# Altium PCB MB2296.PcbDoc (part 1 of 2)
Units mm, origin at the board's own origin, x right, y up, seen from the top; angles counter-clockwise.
Board outline 43 x 47.02 mm, 4 copper layers (Top Layer, Internal 1, Internal 2, Bottom Layer), stack 1.565 mm thick; 91 components, 90 nets, 355 pads, 438 vias.
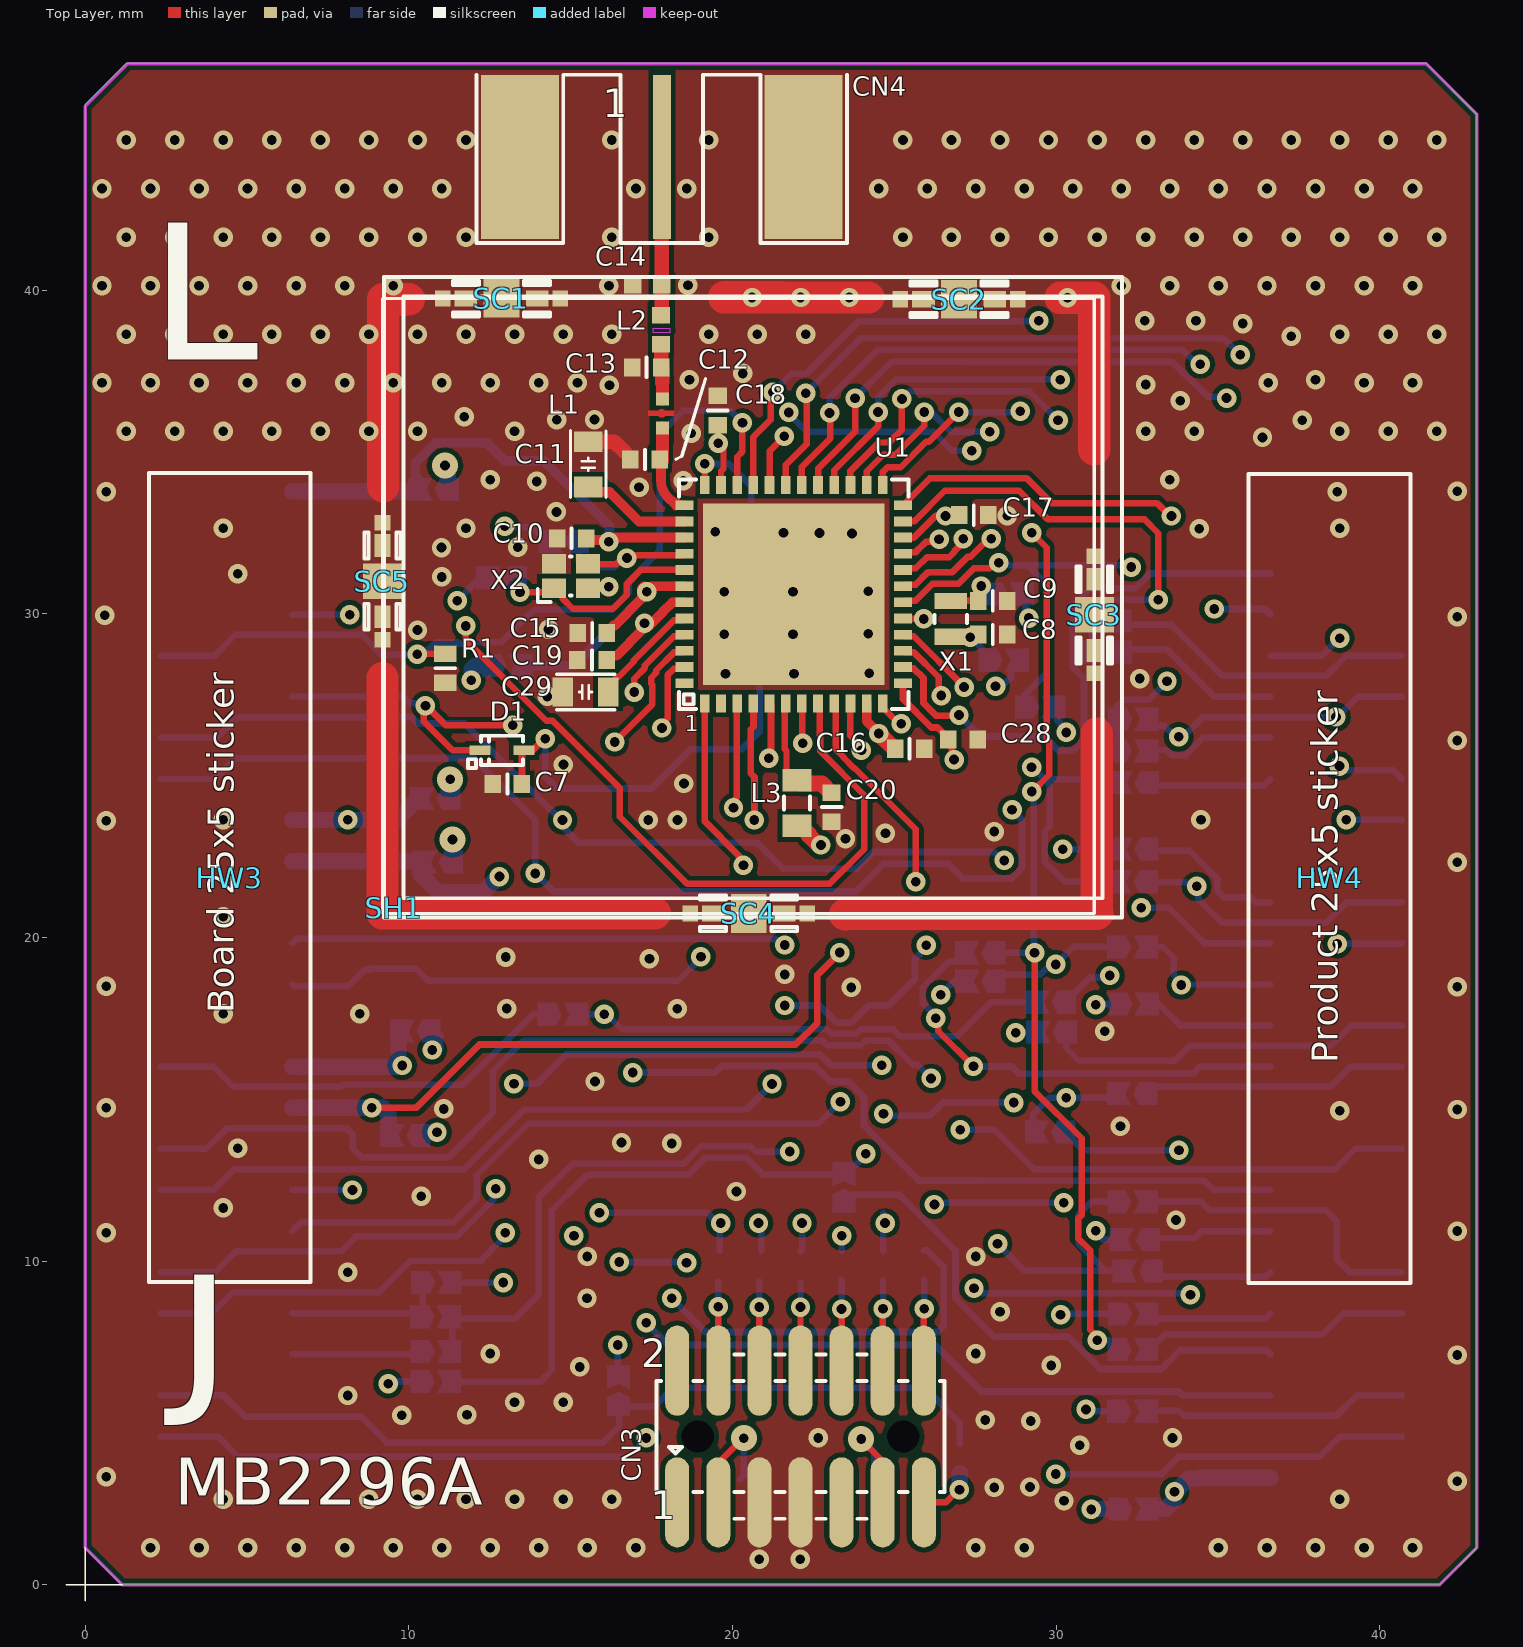
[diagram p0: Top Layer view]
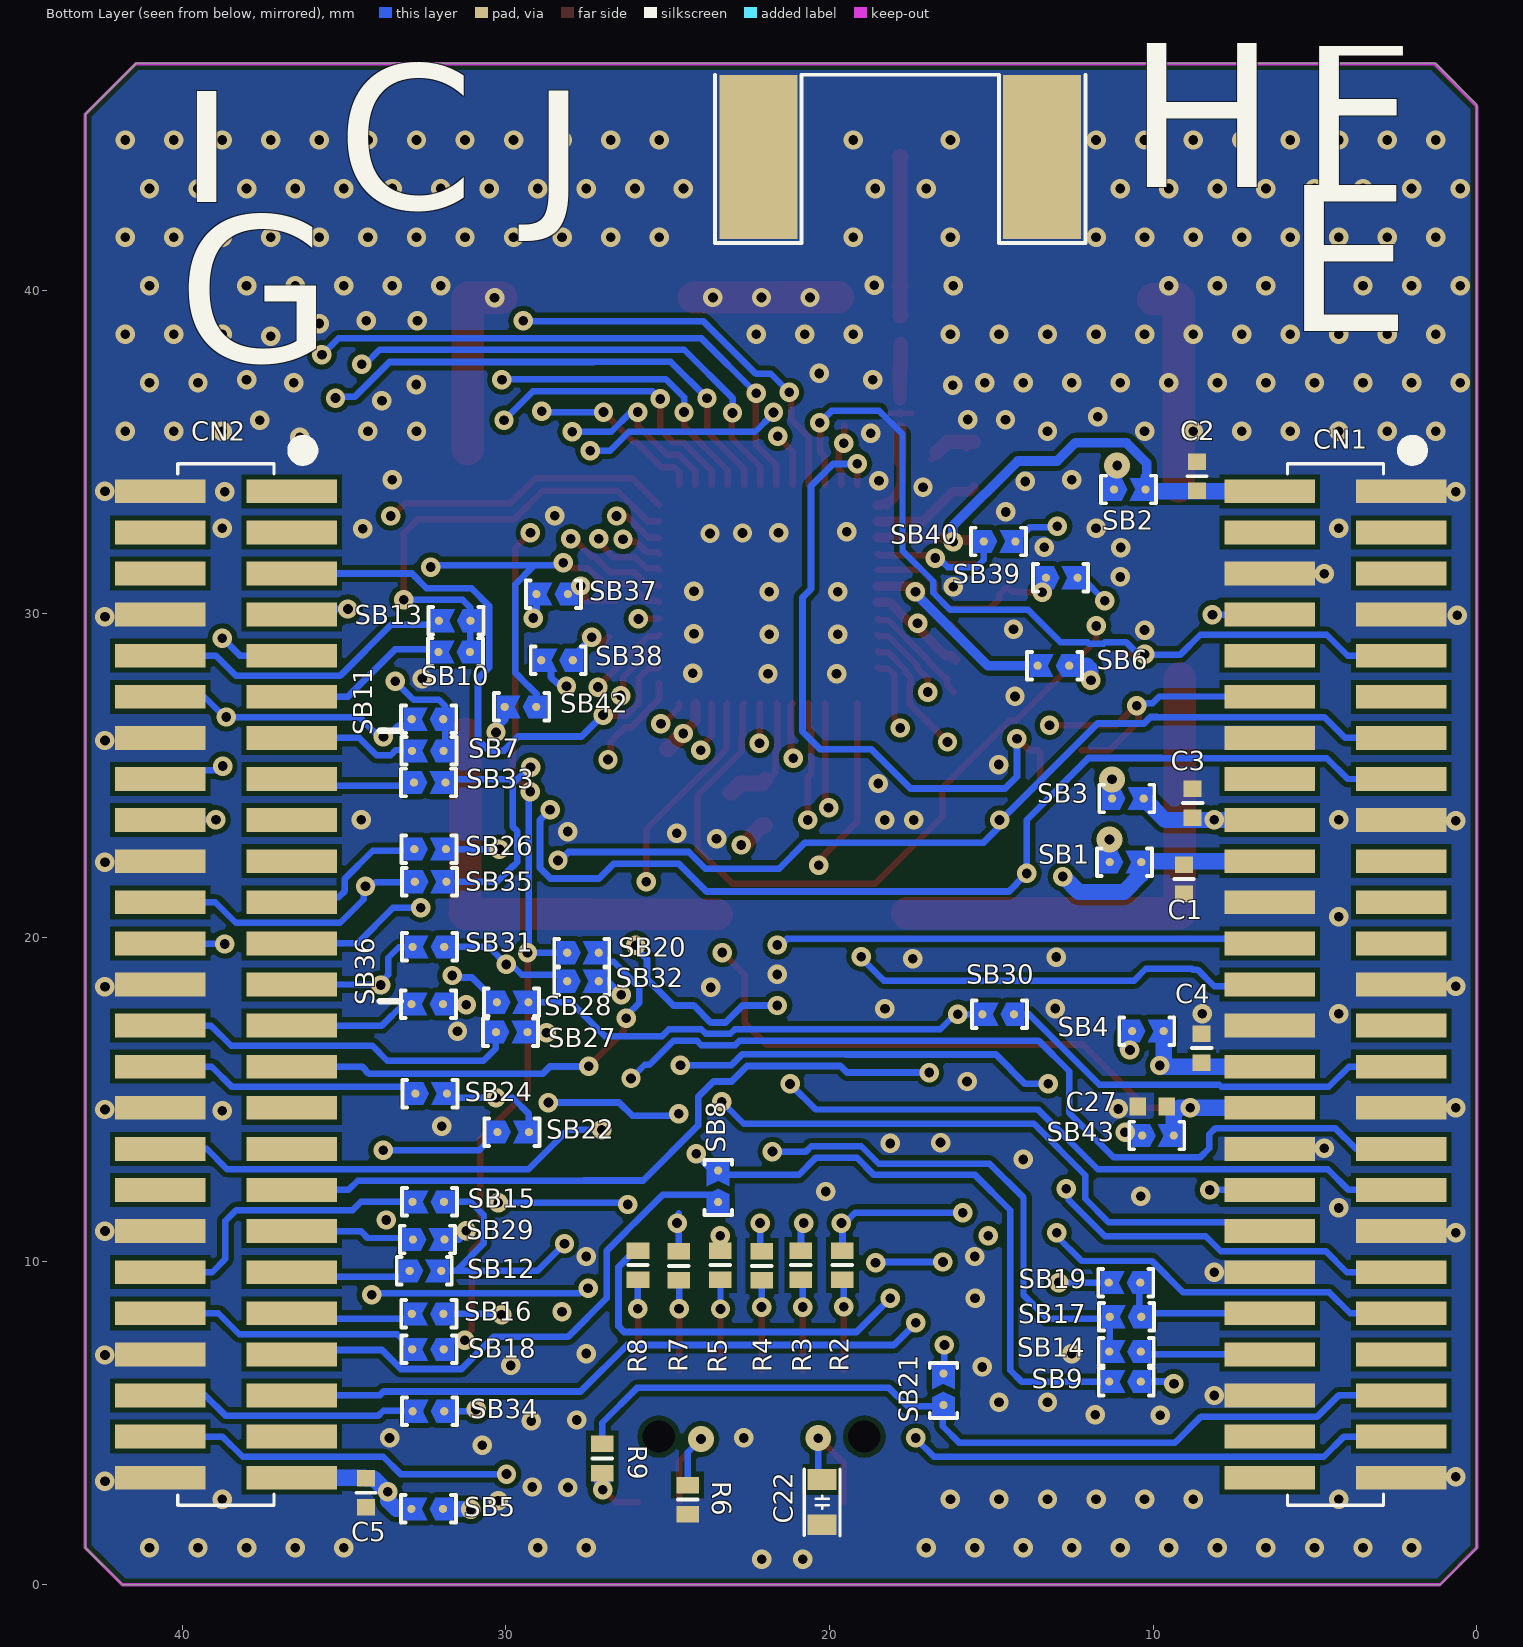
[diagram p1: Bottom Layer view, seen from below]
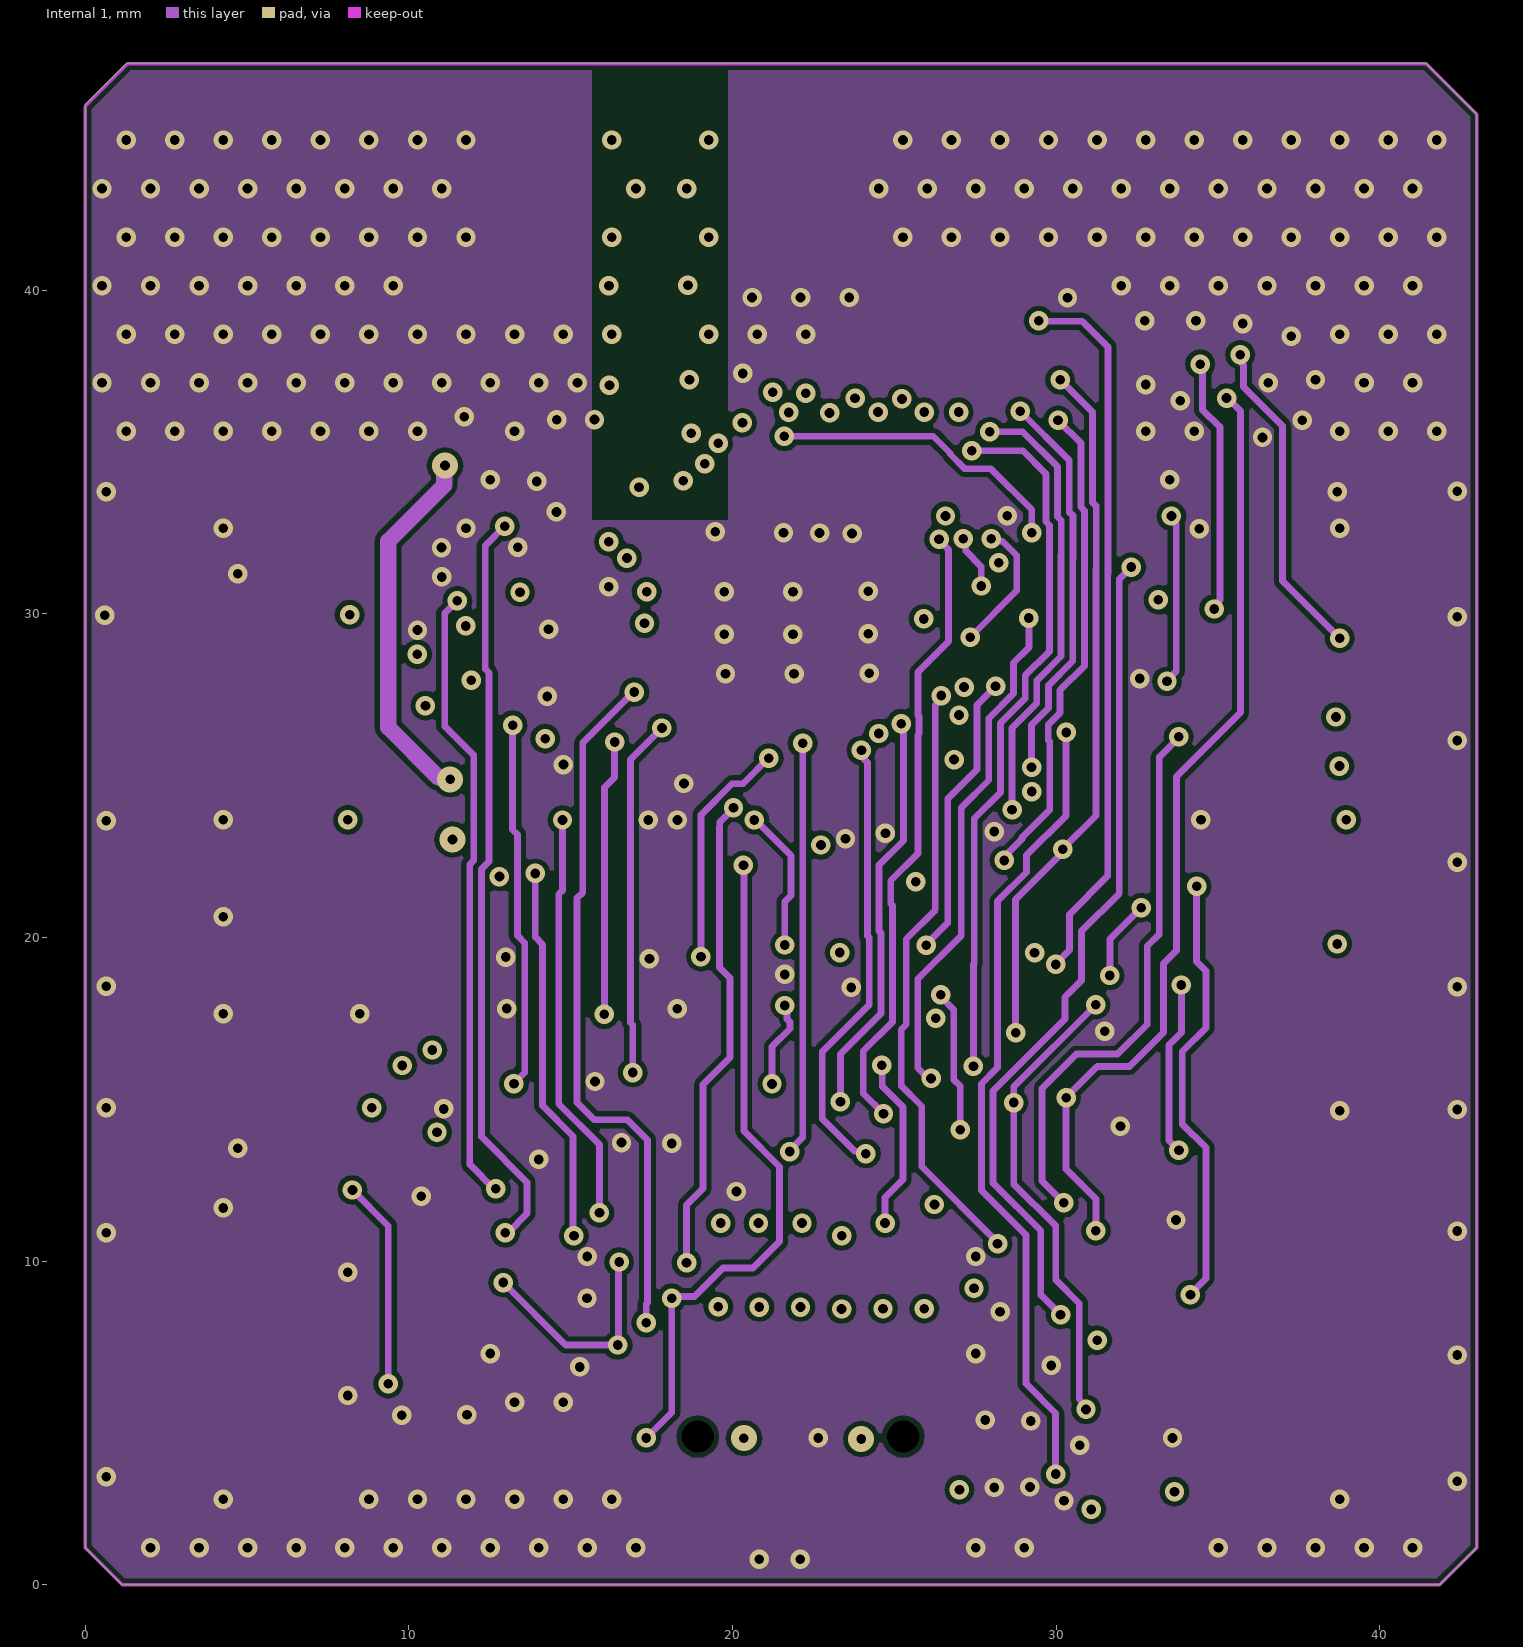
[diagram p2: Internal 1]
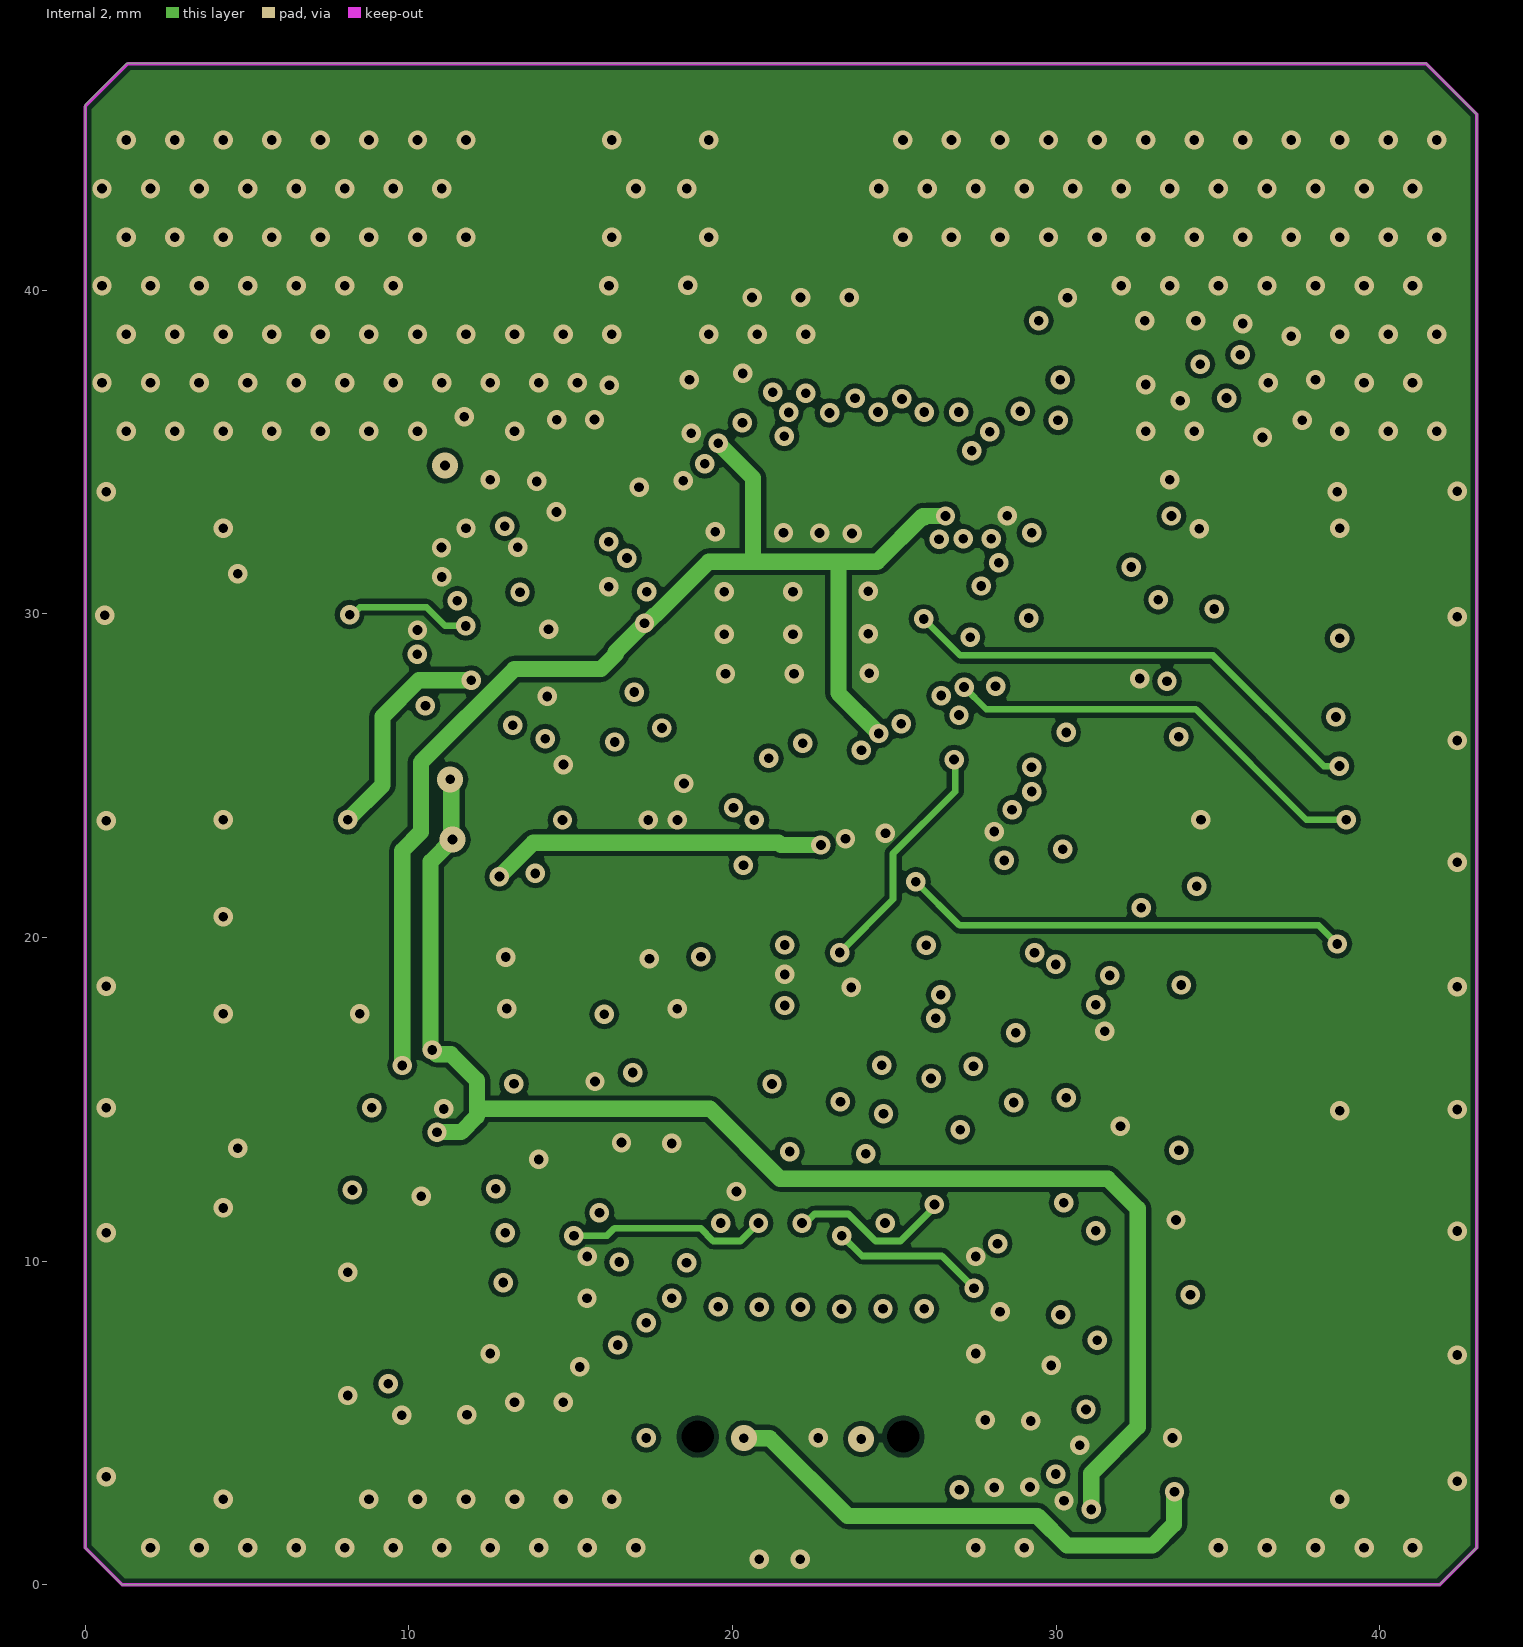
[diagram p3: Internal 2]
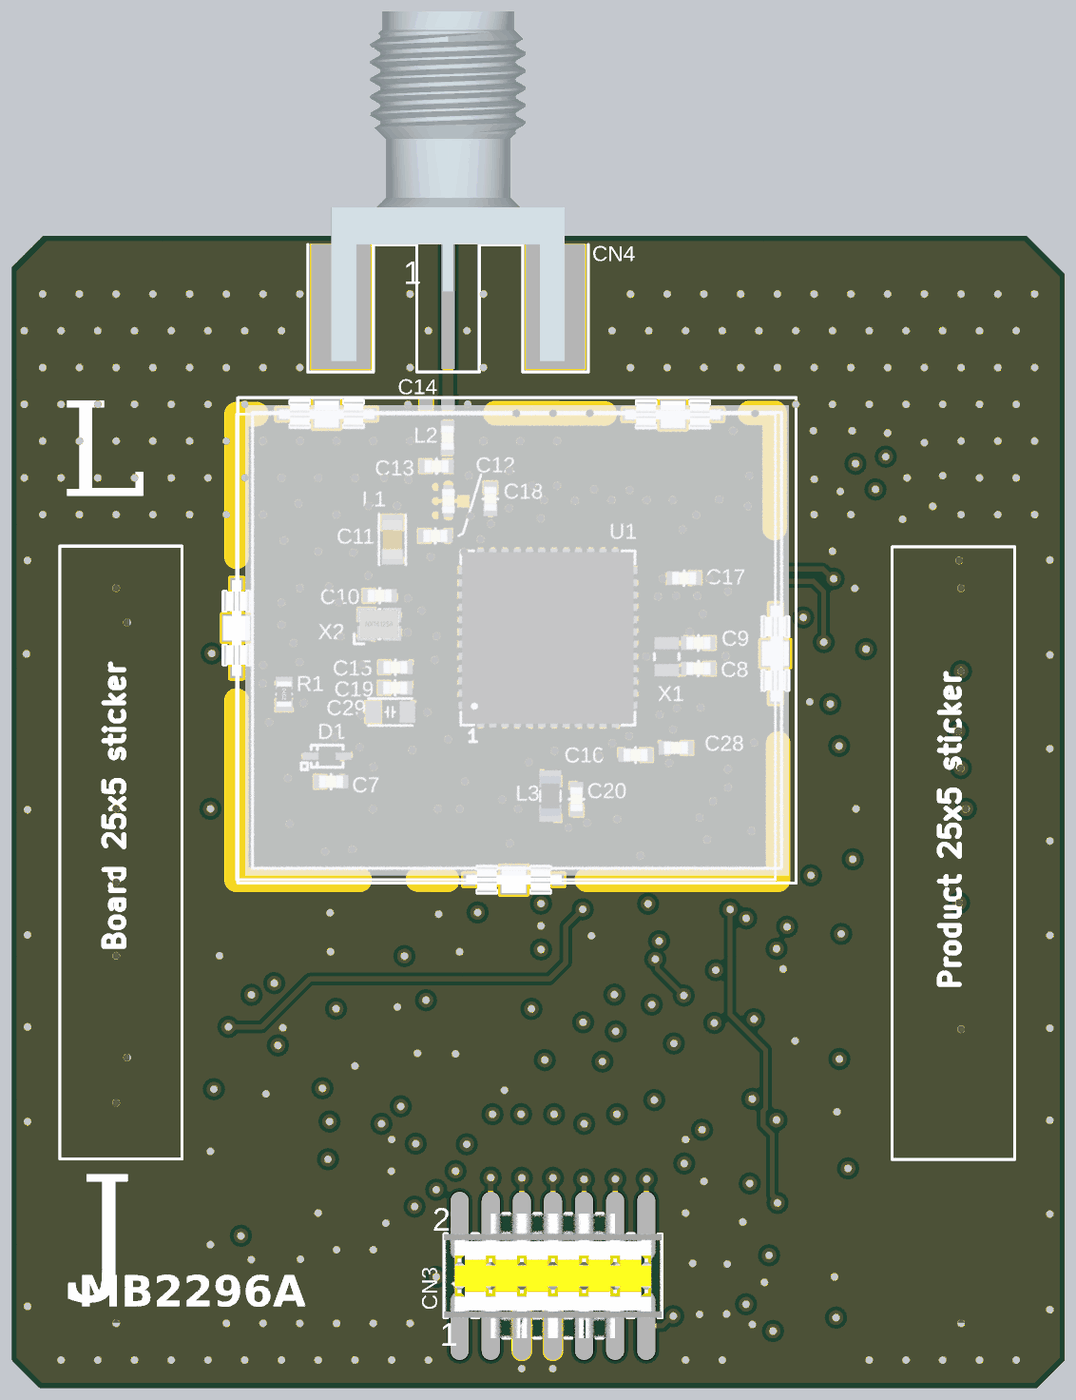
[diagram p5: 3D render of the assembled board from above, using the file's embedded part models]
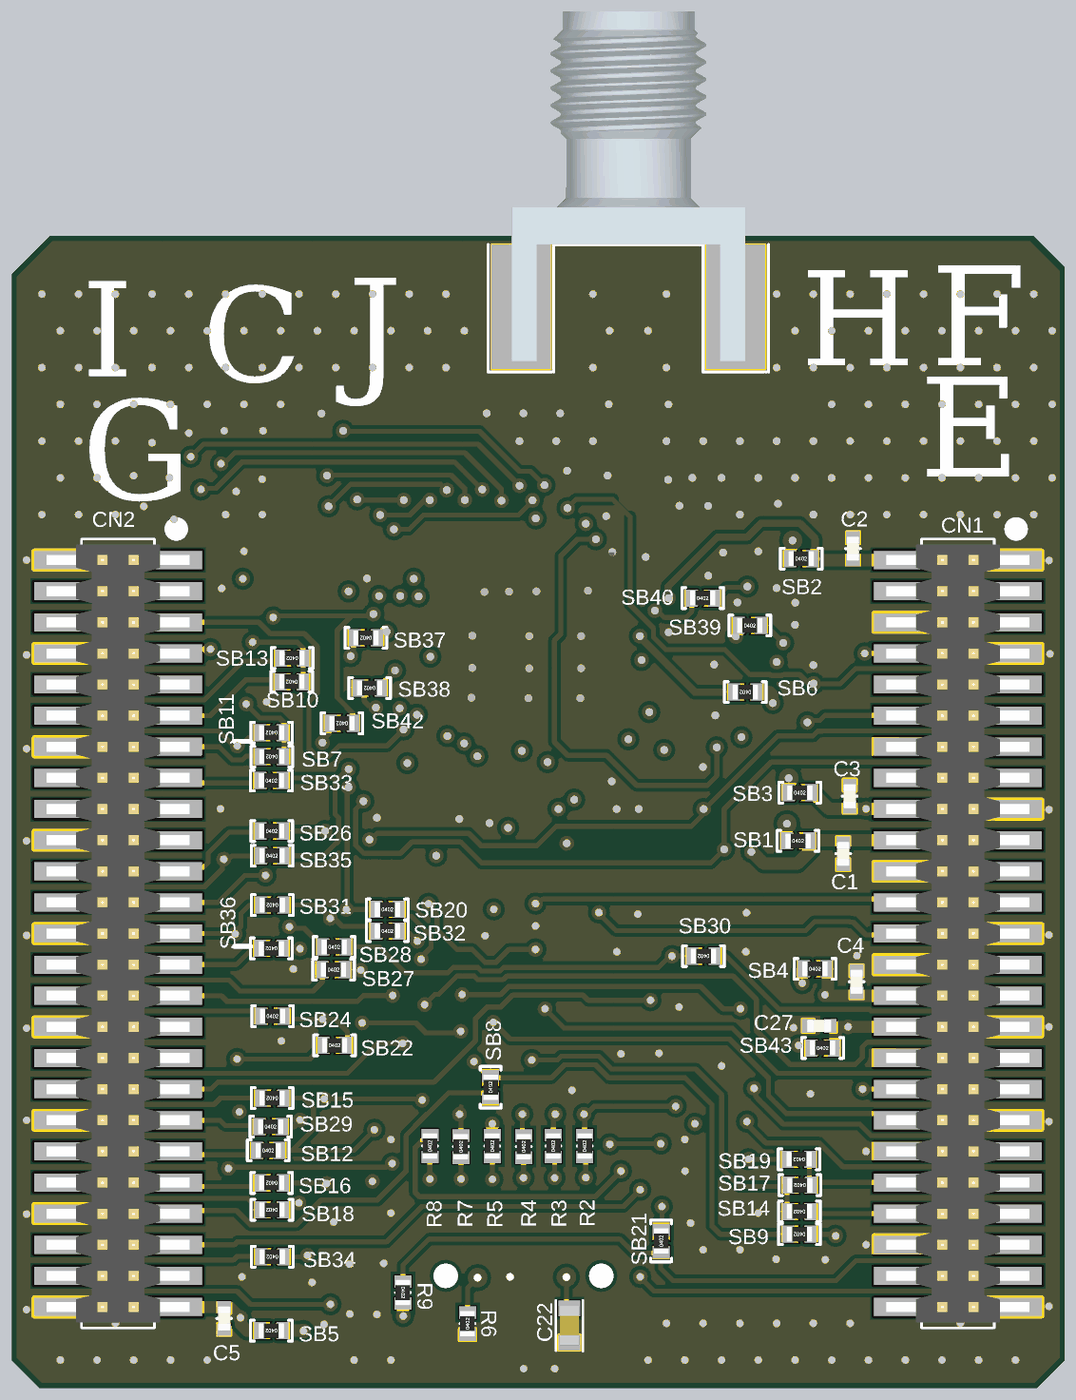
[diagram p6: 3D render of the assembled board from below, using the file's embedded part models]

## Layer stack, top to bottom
Top Solder: solder mask 0.0178, Solder Resist, Dk 4.2
Top Layer: signal copper 0.0406
Dielectric 1: core 0.0762, FR-4, Dk 3.7
Internal 1: signal copper 0.0305
Dielectric 3: prepreg 1.27, Dk 4.5
Internal 2: signal copper 0.0305
Dielectric 2: core 0.0762, FR-4, Dk 3.7
Bottom Layer: signal copper 0.0406
Bottom Solder: solder mask 0.0178, Solder Resist, Dk 4.2

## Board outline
0,1.139 1.139,0 41.852,0 43.001,1.141 43,39.982 43,45.443 41.427,47.015 1.273,47.015 0.003,45.745 0,45.72

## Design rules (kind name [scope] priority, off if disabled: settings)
Clearance "RF Path IPD" [WithinRoom('IPD')] p1: gap=0 ignorepadtopadclearanceinfootprint=FALSE
Clearance "RF Path 3" [InNet('NetC12_2')] p2: gap=0.13 ignorepadtopadclearanceinfootprint=FALSE
Clearance "RF Path 2" [InNet('NetC13_2')] p3: gap=0.13 ignorepadtopadclearanceinfootprint=FALSE
Clearance "RF Path 1" [InNet('ANT')] p4: gap=0.13 ignorepadtopadclearanceinfootprint=FALSE
Clearance [All] p5: gap=0.15 ignorepadtopadclearanceinfootprint=FALSE
ComponentClearance [All] p1: gap=0.1 collisioncheckmode=3 verticalgap=0.1 showdistances=FALSE
HoleSize [All] p1: absolutevalues=TRUE maxlimit=10 minlimit=0.025 maxpercent=80.000 minpercent=20.000
MatchedLengths "Schematic Matched Net Lengths_1" [InNet('GPIO36')] p1: tolerance=2 checknetsindiffpair=TRUE checkdiffpairvsdiffpair=FALSE checkxsignals=FALSE checkothers=FALSE
MatchedLengths "Schematic Matched Net Lengths" [InNet('GPIO35')] p2: tolerance=2 checknetsindiffpair=TRUE checkdiffpairvsdiffpair=FALSE checkxsignals=FALSE checkothers=FALSE
MaxMinImpedance "Schematic Impedance Constraint_1" [InNet('GPIO36')] p1: minimum=85.00 maximum=95.00
MaxMinImpedance "Schematic Impedance Constraint" [InNet('GPIO36')] p2: minimum=85.00 maximum=95.00
MinimumSolderMaskSliver [All] p1: minsoldermaskwidth=0.1
PlaneConnect [All] p1: planeconnectstyle=Relief reliefexpansion=0.508 reliefentries=4 reliefconductorwidth=0.21 reliefairgap=0.21
PolygonConnect Path_RF [InNet('NetC12_2')] p1: connectstyle=Direct reliefconductorwidth=0.254 reliefentries=4 polygonreliefangle="90 Angle" airgapwidth=0.254
PolygonConnect PolygonConnect_via [IsVia] p2: connectstyle=Direct reliefconductorwidth=0.254 reliefentries=4 polygonreliefangle="90 Angle" airgapwidth=0.254
PolygonConnect General [All] p3: connectstyle=Direct reliefconductorwidth=0.2 reliefentries=4 polygonreliefangle="90 Angle" airgapwidth=0.2
RoomDefinition IPD [False vs False] p1: confinementstyle=ConfineIn formatcopy=TRUE lockcomponents=FALSE outline 17.16,37.15 18.47,37.15 18.47,35.271 17.16,35.271
RoutingVias [All] p1: holewidth=0.3 width=0.6 viastyle="Through Hole" minholewidth=0.2 minwidth=0.5 maxholewidth=3.5 maxwidth=6.5
ShortCircuit [WithinRoom('IPD')] p1: allowed=TRUE
SilkToSilkClearance [All] p1 off: silktosilkclearance=0.2
SilkToSolderMaskClearance [IsPad] p1 off: minsilkscreentomaskgap=0.2 clearancetoexposedcopper=TRUE
SolderMaskExpansion [All] p1: expansion=0.102 istentingtop=FALSE
Width [All] p1: maxlimit=6 minlimit=0.15 preferedwidth=0.2 midlayer1_maxwidth=0.512 midlayer2_maxwidth=0.512 minimp=50.000000 maximp=50.000000 favimp=50.000000
23 further rules are at their usual default settings.

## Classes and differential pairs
component class "STM32 microcontroller I/Os & Clock": C1 C2 C3 C4 C5 C7 C8 C9 C27 CN1 CN2 D1 R1 SB1 SB2 SB3 SB4 SB5 SB7 SB8 SB9 SB10 SB11 SB12 SB13 SB14 SB15 SB16 SB17 SB18 SB19 SB20 SB21 SB22 SB24 SB26 SB27 SB28 SB29 SB30 SB31 SB32 SB33 SB34 SB35 SB36 SB37 SB38 SB39 SB40 SB42 SB43 U1 X1 X2
component class "RF & Power Management Schematic": C10 C11 C12 C13 C14 C15 C16 C17 C18 C19 C20 C22 C28 C29 CN3 CN4 L1 L2 L3 R2 R3 R4 R5 R6 R7 R8 R9 SB6 SC1 SC2 SC3 SC4 SC5 SH1
component class Project_Overview: HW2 HW3 HW4

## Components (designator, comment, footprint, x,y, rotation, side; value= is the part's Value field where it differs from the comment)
C1 "Capacitor" C0402#1 9.05,21.804 r90 bottom value=1uF
C2 "Capacitor" C0402#1 8.649,34.255 r270 bottom value=1uF
C3 "Capacitor" C0402#1 8.782,24.151 r270 bottom value=1uF
C4 "Capacitor" C0402#1 8.504,16.581 r270 bottom value=1uF
C5 "Capacitor" C0402#1 34.325,2.841 r90 bottom value=1uF
C7 "Capacitor" C0402#1 13.042,24.745 r0 top value=100nF
C8 "Capacitor" C0402#1 28.042,29.362 r180 top value=6pF
C9 "Capacitor" C0402#1 28.042,30.404 r180 top value=6pF
C10 "Capacitor" C0402#1 15.028,32.334 r180 top value=100nF
C11 "Capacitor" C0603 15.545,34.62 r270 top value=470nF
C12 "Capacitor" C0402#1 17.297,34.773 r0 top value=1.5pF
C13 "Capacitor" C0402#1 17.348,37.617 r0 top value=1.8pF
C14 "Capacitor" C0402_MURATA_GRM155_H0P5 17.366,40.157 r0 top value=1pF
C15 "Capacitor" C0402#1 15.668,29.414 r180 top value=100nF
C16 "Capacitor" C0402#1 25.474,25.831 r0 top value=100nF
C17 "Capacitor" C0402#1 27.457,33.052 r0 top value=100nF
C18 "Capacitor" C0402#1 19.546,36.287 r90 top value=100nF
C19 "Capacitor" C0402#1 15.658,28.575 r180 top value=100nF
C20 "Capacitor" C0402#1 23.063,24.028 r90 top value=1uF
C22 "Capacitor" C0603 20.231,2.554 r90 bottom value=1uF
C27 "Capacitor" C0402#1 10.029,14.782 r180 bottom value=1uF
C28 "Capacitor" C0402#1 27.123,26.124 r0 top value=100nF
C29 "Capacitor" C0603_H0P8 15.459,27.586 r180 top value=4.7uF
CN1 "FTSH-125-02-L-DV" FTSH-125-02-L-DV 4.366,18.548 r180 bottom locked value="Header 25x2"
CN2 "FTSH-125-02-L-DV" FTSH-125-02-L-DV 38.656,18.548 r180 bottom locked value="Header 25x2"
CN3 "Header 7x2" CON_SAMTEC_FTSH-107-01-L-DV-K-A 22.101,4.579 r0 top
CN4 "mmcx" CON_SMA-RF_CINCH_142-0701-851 17.819,46.66 r0 top value=Jack_SMA_142-0701-851
D1 "SCHOTTKY_1A_2K" DIO_SOD523_1A_2K 12.879,25.784 r180 top value=BAT54KFILM
HW3 "STICKER_BOARD" STICKER_BOARD_25X5 4.464,21.854 r90 top value="Sticker board"
HW4 "STICKER_PRODUCT" STICKER_PRODUCT_25X5 38.451,21.829 r90 top value="Sticker product"
L1 "Inductor" C0402#2 17.831,36.195 r90 top value=1.8nH
L2 "Inductor" C0402#1 17.796,38.776 r90 top value=3.3nH
L3 "Inductor" IND_0603_H0P8 21.995,24.159 r90 top value="47R @ 100MHz"
R1 "Resistor" R0402 11.125,28.32 r270 top value=100K
R2 "Resistor" R0402 19.605,9.878 r90 bottom value=47R
R3 "Resistor" R0402 20.887,9.878 r90 bottom value=47R
R4 "Resistor" R0402 22.092,9.852 r90 bottom value=47R
R5 "Resistor" R0402 23.376,9.878 r90 bottom value=47R
R6 "Resistor" R0402 24.386,2.631 r90 bottom value=47R
R7 "Resistor" R0402 24.658,9.853 r90 bottom value=47R
R8 "Resistor" R0402 25.922,9.878 r90 bottom value=47R
R9 "Resistor" R0402 27.024,3.9 r270 bottom value=47R
SB1 "SB_OFF" SOLDER-BRIDGE_R0402-0R 10.893,22.329 r180 bottom
SB2 "SB_OFF" SOLDER-BRIDGE_R0402-0R 10.764,33.846 r180 bottom
SB3 "SB_OFF" SOLDER-BRIDGE_R0402-0R 10.819,24.295 r180 bottom
SB4 "SB_OFF" SOLDER-BRIDGE_R0402-0R 10.201,17.107 r180 bottom
SB5 "SB_OFF" SOLDER-BRIDGE_R0402-0R 32.397,2.343 r0 bottom
SB6 "SB_ON" SOLDER-BRIDGE_R0402-0R 13.046,28.401 r0 bottom
SB7 "SB_ON" SOLDER-BRIDGE_R0402-0R 32.378,25.767 r0 bottom
SB8 "SB_ON" SOLDER-BRIDGE_R0402-0R 23.444,12.277 r90 bottom
SB9 "SB_OFF" SOLDER-BRIDGE_R0402-0R 10.834,6.277 r0 bottom
SB10 "SB_ON" SOLDER-BRIDGE_R0402-0R 31.563,28.823 r0 bottom
SB11 "SB_ON" SOLDER-BRIDGE_R0402-0R 32.389,26.746 r0 bottom
SB12 "SB_OFF" SOLDER-BRIDGE_R0402-0R 32.525,9.698 r180 bottom
SB13 "SB_ON" SOLDER-BRIDGE_R0402-0R 31.548,29.789 r0 bottom
SB14 "SB_OFF" SOLDER-BRIDGE_R0402-0R 10.834,7.205 r0 bottom
SB15 "SB_ON" SOLDER-BRIDGE_R0402-0R 32.364,11.832 r0 bottom
SB16 "SB_OFF" SOLDER-BRIDGE_R0402-0R 32.385,8.371 r0 bottom
SB17 "SB_ON" SOLDER-BRIDGE_R0402-0R 10.82,8.28 r0 bottom
SB18 "SB_ON" SOLDER-BRIDGE_R0402-0R 32.373,7.274 r0 bottom
SB19 "SB_OFF" SOLDER-BRIDGE_R0402-0R 10.85,9.337 r0 bottom
SB20 "SB_OFF" SOLDER-BRIDGE_R0402-0R 27.658,19.531 r180 bottom
SB21 "SB_ON" SOLDER-BRIDGE_R0402-0R 16.481,6.002 r90 bottom
SB22 "SB_OFF" SOLDER-BRIDGE_R0402-0R 29.816,13.988 r180 bottom
SB24 "SB_ON" SOLDER-BRIDGE_R0402-0R 32.35,15.176 r180 bottom
SB26 "SB_ON" SOLDER-BRIDGE_R0402-0R 32.383,22.731 r180 bottom
SB27 "SB_OFF" SOLDER-BRIDGE_R0402-0R 29.86,17.075 r180 bottom
SB28 "SB_OFF" SOLDER-BRIDGE_R0402-0R 29.832,18 r180 bottom
SB29 "SB_ON" SOLDER-BRIDGE_R0402-0R 32.427,10.668 r180 bottom
SB30 "SB_ON" SOLDER-BRIDGE_R0402-0R 14.754,17.628 r0 bottom
SB31 "SB_ON" SOLDER-BRIDGE_R0402-0R 32.36,19.71 r0 bottom
SB32 "SB_OFF" SOLDER-BRIDGE_R0402-0R 27.658,18.65 r180 bottom
SB33 "SB_ON" SOLDER-BRIDGE_R0402-0R 32.394,24.789 r180 bottom
SB34 "SB_ON" SOLDER-BRIDGE_R0402-0R 32.36,5.359 r0 bottom
SB35 "SB_OFF" SOLDER-BRIDGE_R0402-0R 32.367,21.723 r180 bottom
SB36 "SB_OFF" SOLDER-BRIDGE_R0402-0R 32.396,17.941 r0 bottom
SB37 "SB_OFF" SOLDER-BRIDGE_R0402-0R 28.537,30.612 r0 bottom
SB38 "SB_OFF" SOLDER-BRIDGE_R0402-0R 28.386,28.569 r0 bottom
SB39 "SB_OFF" SOLDER-BRIDGE_R0402-0R 12.862,31.117 r180 bottom
SB40 "SB_OFF" SOLDER-BRIDGE_R0402-0R 14.785,32.238 r180 bottom
SB42 "SB_ON" SOLDER-BRIDGE_R0402-0R 29.515,27.127 r0 bottom
SB43 "SB_OFF" SOLDER-BRIDGE_R0402-0R 9.891,13.88 r180 bottom
SC1 "Shield-clip_S0951-46R" CLIP_HARWIN_S0951-46R#1 12.862,39.742 r180 top value=S0951-46R
SC2 "Shield-clip_S0951-46R" CLIP_HARWIN_S0951-46R#2 27,39.726 r180 top value=S0951-46R
SC3 "Shield-clip_S0951-46R" CLIP_HARWIN_S0951-46R#2 31.182,29.971 r90 top value=S0951-46R
SC4 "Shield-clip_S0951-46R" CLIP_HARWIN_S0951-46R#2 20.502,20.745 r180 top value=S0951-46R
SC5 "Shield-clip_S0951-46R" CLIP_HARWIN_S0951-46R#2 9.185,31.013 r90 top value=S0951-46R
SH1 "RF Shield (22.2x19.2x2mm)" SHIELD_RF_ST-CUSTOM_22P2X19P2_H2 9.536,20.913 r0 top
U1 "STM32WBA62CIU6" STM32WB62CGU6 18.645,27.208 r0 top locked
X1 "XTAL_2_PINS" CRY_NX1610SE_2P 26.746,29.845 r270 top value=32.768kHz
X2 "XTAL_4_PINS" CRY_NX1612SA_4P 15.009,31.172 r0 top value=32MHz

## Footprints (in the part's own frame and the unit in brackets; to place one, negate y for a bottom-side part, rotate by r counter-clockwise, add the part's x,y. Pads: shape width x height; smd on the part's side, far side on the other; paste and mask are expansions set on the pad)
C0402#1 [mm]
  rect 0.51x0.56 smd mask+0.05: 1(-0.45,0) 2(0.45,0)
  silkscreen extent 0,-0.3 0,0.3, body extent -0.5,-0.3 0.5,0.3, height 0.4
C0402#2 [mm]
  rect 0.4x0.4 smd mask+0.05: 1(-0.45,0) 2(0.45,0)
  body extent -0.5,-0.3 0.5,0.3, height 0.4
C0402_MURATA_GRM155_H0P5 [mm]
  rect 0.55x0.5 smd mask+0.05: 1(-0.45,0) 2(0.45,0)
  body extent -0.53,-0.28 0.53,0.27, height 0.55
C0603 [mm]
  rect 0.64x0.89 smd mask+0.05: 1(-0.7,0) 2(0.7,0)
  silkscreen extent -1.05,-0.55 1.02,0.55, body extent -0.9,-0.5 0.9,0.5, height 1.4
C0603_H0P8 [mm]
  rect 0.64x0.89 smd mask+0.05: 1(-0.7,0) 2(0.7,0)
  silkscreen extent -0.9,-0.55 0.9,0.55, body extent -0.9,-0.5 0.9,0.5, height 1
CLIP_HARWIN_S0951-46R#1 [mm] "MCD-01587_CLIP-X1"
  rect 0.48x0.5 smd mask+0.1: 1(-1.81,0) 1(1.81,0)
  rect 0.7x0.5 smd mask+0.1: 1(-1.1,0) 1(1.1,0)
  rect 1.1x1.2 smd mask+0.1: 1(0,-0.013)
  silkscreen extent -1.5,-0.55 1.5,0.55, body extent -2.05,-0.65 2.05,0.65, height 1.28
CLIP_HARWIN_S0951-46R#2 [mm] "MCD-01587_CLIP-X1"
  rect 0.48x0.5 smd mask+0.1: 1(-1.81,0) 1(1.81,0)
  rect 0.7x0.5 smd mask+0.1: 1(-1.1,0) 1(1.1,0)
  rect 1.1x1.2 smd mask+0.1: 1(0,0)
  silkscreen extent -1.5,-0.55 1.5,0.55, body extent -2.05,-0.65 2.05,0.65, height 1.28
CON_SAMTEC_FTSH-107-01-L-DV-K-A [mm] "MCD-01959"
  oval 0.74x2.79 smd mask+0.05: 1(-3.81,-2.035) 2(-3.81,2.035) 3(-2.54,-2.035) 4(-2.54,2.035) 5(-1.27,-2.035) 6(-1.27,2.035) 7(0,-2.035) 8(0,2.035) 9(1.27,-2.035) 10(1.27,2.035) 11(2.54,-2.035) 12(2.54,2.035) 13(3.81,-2.035) 14(3.81,2.035)
  round 0 hole 1 unplated paste-2539.97 mask+0.05: NPTH1(-3.175,0) NPTH2(3.175,0)
  silkscreen extent -4.44,-2.54 4.44,2.54, body extent -4.44,-2.92 4.45,2.92, height 6.12
CON_SMA-RF_CINCH_142-0701-851 [mil] "MCD-02072"
  rect 21.65x200 smd mask+1.97: 1(0,-100)
  rect 95x200 smd mask+1.97: 2(172.48,-100) 3(-172.48,-100)
  rect 95x200 smd far side mask+1.97: 4(-172.48,-100) 5(172.48,-100)
  silkscreen extent -225,-205 225,0, body extent -189,-187 189,376, height 161
CRY_NX1610SE_2P [mm] "MCD-02291"
  rect 0.5x1 smd mask+0.05: 1(-0.55,0) 2(0.55,0)
  silkscreen extent -0.13,-0.5 0.13,0.5, body extent -0.8,-0.5 0.8,0.5, height 0.45
CRY_NX1612SA_4P [mm] "MCD-02262"
  rect 0.75x0.6 smd mask+0.038: 1(-0.525,-0.375) 2(0.525,-0.375) 3(0.525,0.375) 4(-0.525,0.375)
  silkscreen extent -1.02,-0.8 0.03,0.6, body extent -0.8,-0.6 0.8,0.6, height 0.51
DIO_SOD523_1A_2K [mm] "MCD-01677"
  rect 0.65x0.3 smd mask+0.05: 1(-0.675,0) 2(0.675,0)
  silkscreen extent -0.65,-0.45 1.05,0.55, body extent -0.85,-0.45 0.85,0.45, height 0.71
FTSH-125-02-L-DV [mil] "Header2x25 Reverse 1.27mm SAMTEC (FTSH-125-02-L-DV)"
  rect 110x29.02 smd: 1(80,600) 2(-80,600) 3(80,550) 4(-80,550) 5(80,500) 6(-80,500) 7(80,450) 8(-80,450) 9(80,400) 10(-80,400) 11(80,350) 12(-80,350) 13(80,300) 14(-80,300) 15(80,250) 16(-80,250) 17(80,200) 18(-80,200) 19(80,150) 20(-80,150) 21(80,100) 22(-80,100) 23(80,50) 24(-80,50) 25(80,0) 26(-80,0) 27(80,-50) 28(-80,-50) 29(80,-100) 30(-80,-100) 31(80,-150) 32(-80,-150) 33(80,-200) 34(-80,-200) 35(80,-250) 36(-80,-250) 37(80,-300) 38(-80,-300) 39(80,-350) 40(-80,-350) 41(80,-400) 42(-80,-400) 43(80,-450) 44(-80,-450) 45(80,-500) 46(-80,-500) 47(80,-550) 48(-80,-550) 49(80,-600) 50(-80,-600)
  silkscreen extent -58,-633 103,659, body extent -115,-625 115,625, height 190
IND_0603_H0P8 [mm]
  rect 0.7x0.9 smd mask+0.05: 1(-0.7,0) 2(0.7,0)
  silkscreen extent -0.2,-0.4 0.2,0.4, body extent -0.8,-0.4 0.8,0.4, height 0.8
R0402 [mm]
  rect 0.51x0.7 smd mask+0.05: 1(-0.45,0) 2(0.45,0)
  silkscreen extent 0,-0.3 0,0.3, body extent -0.52,-0.3 0.52,0.3, height 0.4
SHIELD_RF_ST-CUSTOM_22P2X19P2_H2 [mm] "MCD-02088"
  silkscreen extent -0.3,-0.3 22.5,19.5, body extent 0,0 22.2,19.2, height 2.45
SOLDER-BRIDGE_R0402-0R [mil] "MCD-01619"
  round 10 smd paste-393.7: 1(-17.72,0) 2(20.67,0)
  Top Layer region: -30.51,-13.78 -30.51,13.78 -8.37,13.78 -1.48,0 -8.37,-13.78
  Top Layer region: 1.48,13.78 8.37,0 1.48,-13.78 30.51,-13.78 30.51,13.78
  silkscreen extent -33,-17 33,17, body extent -20,-12 20,12, height 14
STICKER_BOARD_25X5 [mm] "Sticker to mention board reference + serial number"
  silkscreen extent -12.5,-2.5 12.5,2.5, body extent -12.5,-2.5 12.5,2.5, height 0.01
STICKER_PRODUCT_25X5 [mm] "Sticker to mention board CPN code"
  silkscreen extent -12.5,-2.5 12.5,2.5
STM32WB62CGU6 [mm] "STM32WB62CGU6   QFN48  USB  LDO"
  rect 0.3x0.55 smd mask+0.05: 1(0.5,0.025) 2(1,0.025) 3(1.5,0.025) 4(2,0.025) 5(2.5,0.025) 6(3,0.025) 7(3.5,0.025) 8(4,0.025) 9(4.5,0.025) 10(5,0.025) 11(5.5,0.025) 12(6,0.025) 25(6,6.775) 26(5.5,6.775) 27(5,6.775) 28(4.5,6.775) 29(4,6.775) 30(3.5,6.775) 31(3,6.775) 32(2.5,6.775) 33(2,6.775) 34(1.5,6.775) 35(1,6.775) 36(0.5,6.775)
  rect 0.55x0.3 smd mask+0.05: 13(6.625,0.65) 14(6.625,1.15) 15(6.625,1.65) 16(6.625,2.15) 17(6.625,2.65) 18(6.625,3.15) 19(6.625,3.65) 20(6.625,4.15) 21(6.625,4.65) 22(6.625,5.15) 23(6.625,5.65) 24(6.625,6.15) 37(-0.125,6.15) 38(-0.125,5.65) 39(-0.125,5.15) 40(-0.125,4.65) 41(-0.125,4.15) 42(-0.125,3.65) 43(-0.125,3.15) 44(-0.125,2.65) 45(-0.125,2.15) 46(-0.125,1.65) 47(-0.125,1.15) 48(-0.125,0.65)
  rect 5.6x5.6 smd mask+0.05: 49(3.25,3.4)
  silkscreen extent -0.3,-0.15 6.8,6.95, body extent -0.25,-0.1 6.75,6.9, height 0.65

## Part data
C1 C2 C3 C4 C5 C20 C27: library part MCD-01722, "Capacitor, MLCC, 1uF, 10V, X5R, +/-10%, 0402, T=0.5mm", Manufacturer=YAGEO, Manufacturer_Part_Number=CC0402KRX5R6BB105, Package=0402
C7 C10 C15 C16 C17 C18 C19 C28: library part MCD-00006, "Capacitor, MLCC, 100nF, 16V, X7R, +/-10%, 0402, T=0.5mm", Alternate_Manufacturer=MURATA, Alternate_Manufacturer_Part_Number=GCM155R71C104KA55D, Manufacturer=YAGEO, Manufacturer_Part_Number=CC0402KRX7R7BB104, Package=C0402
C8 C9: library part MCD-03185, "Capacitor, MLCC, 6 pF, 50V, NPO, ±0,25pF, 0402, T=0.5mm", Manufacturer=MURATA, Manufacturer_Part_Number=GJM1555C1H6R0CB01, Package=0402
C11: library part MCD-01006, "Capacitor, MLCC, 470nF, 16V, X7R, +/-10%, 0603, T=0.8mm", Manufacturer=YAGEO, Manufacturer_Part_Number=CC0603KRX7R7BB474, Package=0603
C12: library part MCD-02994, "Capacitor, MLCC, 1.5pF, 50V, C0G, +/-0.25pF, 0402, T=0.5mm", Manufacturer=MURATA, Manufacturer_Part_Number=GRM1555C1H1R5CA01, Package=0402
C13: library part MCD-02995, "Capacitor, MLCC, 1.8pF, 50V, C0G, +/-0.25pF, 0402, T=0.5mm", Manufacturer=MURATA, Manufacturer_Part_Number=GRM1555C1H1R8CA01, Package=0402
C14: library part MCD-03737, "Capacitor, MLCC, 1pF, 50V, C0G, +/-0.1pF, 0402, T=0.5mm", Manufacturer=MURATA, Manufacturer_Part_Number=GJM1555C1H1R0BB01D, Package=0402
C22: library part MCD-00010, "Capacitor, MLCC, 1uF, 16V, X5R, 10%, 0603, T=0,8mm", Manufacturer=YAGEO, Manufacturer_Part_Number=CC0603KRX5R7BB105, Package=C0603
C29: library part MCD-01721, "Capacitor, MLCC, 4.7uF, 10V, X5R, +/-10%, 0603, T=0.8mm", Manufacturer=YAGEO, Manufacturer_Part_Number=CC0603KRX5R6BB475, Package=0603
CN1 CN2: library part MCD-02746, "Header, 25x2, 12.7mm, VR, SMD, T=4.83mm", Manufacturer=SAMTEC
CN3: library part MCD-01531, "Header, 7x2, 1.27mm, VR, T=5.97mm, FTSH series STDC14 without Alignment Pin", Manufacturer=SAMTEC, Manufacturer_Part_Number=FTSH-107-01-L-DV-K
CN4: library part MCD-02072, "Jack_SMA, VR, PCB edge, 50R, T=7.92mm", Alternate_Manufacturer=N/A, Manufacturer=CINCH, Manufacturer_Part_Number=142-0701-851
D1: library part MCD-01677, "Small signal Schottky diodes", Manufacturer=STMICROELECTRONICS, Manufacturer_HQ_COO=EU, Manufacturer_Part_Number=BAT54KFILM, Package=SOD-523
HW3: library part MCD-02190, "Sticker board 25x5 mm", Alternate_Manufacturer=N/A
HW4: library part MCD-02189, "Sticker product 25x5 mm", Alternate_Manufacturer=N/A
L1: library part MCD-02998, "Inductor, 1.8nH, +/-0.3nH, 0.95A, 80mR, 0402, T=0.5mm", Manufacturer=MURATA, Manufacturer_Part_Number=LQG15HS1N8S02, Package=0402
L2: library part MCD-03001, "Inductor, 3.3nH, +/-0.3nH, 0.8A,125mR, 0402, T=0.5mm", Manufacturer=MURATA, Manufacturer_Part_Number=LQG15HS3N3S02, Package=0402
L3: library part MCD-03831, "Ferrite bead, 47R @ 100MHz, +/-25%, 3.5A, 0R02, 0603, T=0.8mm", Manufacturer="TAIYO YUDEN", Manufacturer_Part_Number=LSMGA160808T470RG, Package=0603
R1: library part MCD-00059, "Resistor, 100K, 0402, +/-1%, 1/16W", Manufacturer=YAGEO, Manufacturer_Part_Number=RC0402FR-07100KL, Package=0402
R2 R3 R4 R5 R6 R7 R8 R9: library part MCD-00481, "Resistor,47R,0402,1%,1/16W", Manufacturer=YAGEO, Manufacturer_Part_Number=RC0402FR-0747RL, Package=R0402
SB1 SB2 SB3 SB4 SB5 SB9 SB12 SB14 SB16 SB19 SB20 SB22 SB27 SB28 SB32 SB35 SB36 SB37 SB38 SB39 SB40 SB43: library part MCD-02162, "Solder Bridge 0402 OFF", Manufacturer=YAGEO, Manufacturer_Part_Number=RC0402JR-070RL, Package=SB0402
SB6 SB7 SB8 SB10 SB11 SB13 SB15 SB17 SB18 SB21 SB24 SB26 SB29 SB30 SB31 SB33 SB34 SB42: library part MCD-01618, "Solder Bridge 0402 ON", Manufacturer=YAGEO, Manufacturer_Part_Number=RC0402JR-070RL, Package=SB0402
SC1 SC2 SC3 SC4 SC5: library part MCD-01587, "shield clip Harwin S0951-46R to fix RF shielded cavity", Manufacturer=HARWIN, Manufacturer_Part_Number=S0951-46R
SH1: library part MCD-03256, Manufacturer=TBD
U1: "STM32WBA62CIU6 QFN48_USB_LDO", Manufacturer=STmicroelectronics, Manufacturer_Part_Number=STM32WBA64CIU6
X1: library part MCD-02579, "Crystal, 32.768kHz, 6pF, +/-20ppm, 70KR, 1.6x1mm", Manufacturer=NDK, Manufacturer_Part_Number=NX1610SE-32.768KHZ-EXS00A-MU01501, Package=1.6x1mm
X2: library part MCD-02578, "Crystal, 32MHz, 8pF, +/-10ppm, 40R, 1612(metric), T=0.3mm", Manufacturer=NDK, Manufacturer_Part_Number=NX1612SA-32MHZ-EXS00A-CS09166, Package=1612(metric)

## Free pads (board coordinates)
  round 0.508 on Mech16: 1(21.787,-48.039) 1(70.635,-48.039)

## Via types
v1: diameter 0.6, hole 0.3, Top Layer to Bottom Layer, tented both sides, 433 vias
v2: diameter 0.8, hole 0.3, Top Layer to Bottom Layer, tented both sides, 5 vias

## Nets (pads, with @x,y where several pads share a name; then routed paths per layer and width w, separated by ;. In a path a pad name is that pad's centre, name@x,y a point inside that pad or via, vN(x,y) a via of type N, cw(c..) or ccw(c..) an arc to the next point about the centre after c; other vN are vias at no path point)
GND: C1.1 C2.1 C3.1 C4.1 C5.1 C7.1 C8.1 C9.1 C10.2 C11.1 C12.1 C13.1 C14.1 C15.2 C16.2 C17.2 C18.2 C19.2 C20.1 C22.1 C27.1 C28.2 C29.2 CN1.1 CN1.6 CN1.7 CN1.14 CN1.17 CN1.22 CN1.25 CN1.28 CN1.31 CN1.34 CN1.37 CN1.40 CN1.46 CN1.49 CN2.2 CN2.8 CN2.14 CN2.20 CN2.26 CN2.32 CN2.38 CN2.44 CN2.50 CN3.5 CN3.7 CN4.2 CN4.3 CN4.4 CN4.5 R1.2 R6.1 SC1.1 SC2.1 SC3.1 SC4.1 SC5.1 U1.49 X2.2 X2.4 | length 47.6
  Top Layer w0.2: C11.1@15.545,35.32 C11.1@15.765,35.1 ; C12.1@16.667,35.003 16.692,35.003 16.692,34.928 C12.1@16.847,34.773
  Top Layer w0.45: C11.1@15.545,35.32 15.765,35.32 16.351,35.32 C12.1@16.667,35.003
  Top Layer w1: 9.185,28.007 9.185,20.745 17.596,20.745 ; 9.21,33.949 9.21,38.643 9.21,39.718 9.995,39.718 ; 19.749,39.783 20.21,39.783 21.516,39.78 23.016,39.777 24.194,39.775 ; 23.486,20.711 31.26,20.737 31.26,20.742 ; v1@30.137,39.767 31.179,39.767 31.179,35.093 ; 31.26,26.305 31.26,20.742 ; 31.27,20.742 31.26,20.742
  other v1: 20.826,0.792 22.097,0.792 2.016,1.143 3.516,1.143 5.016,1.143 6.516,1.143 8.016,1.143 9.516,1.143 11.016,1.143 12.516,1.143 14.016,1.143 15.516,1.143 17.016,1.143 27.516,1.143 29.016,1.143 35.016,1.143 36.516,1.143 38.016,1.143 39.516,1.143 41.016,1.143 30.245,2.594 4.266,2.643 8.766,2.643 10.266,2.643 11.766,2.643 13.266,2.643 14.766,2.643 16.266,2.643 38.766,2.643 28.086,3.005 29.192,3.021 42.393,3.2 0.647,3.336 30.734,4.315 22.652,4.537 33.597,4.537 29.217,5.059 27.809,5.09 9.783,5.242 11.793,5.257 13.266,5.643 14.766,5.643 8.116,5.848 15.279,6.73 29.853,6.777 42.393,7.099 12.516,7.143 27.516,7.143 28.269,8.434 15.505,8.852 8.116,9.657 15.516,10.143 27.516,10.143 0.647,10.875 42.393,10.928 33.704,11.272 4.266,11.643 10.384,12.007 20.121,12.152 14.016,13.143 4.712,13.488 18.123,13.638 16.571,13.664 31.988,14.168 38.766,14.643 11.077,14.704 42.393,14.685 0.647,14.738 15.751,15.55 31.499,17.1 4.266,17.643 8.486,17.643 13.023,17.803 18.291,17.803 23.673,18.457 0.647,18.491 42.393,18.475 21.614,18.86 17.434,19.339 12.998,19.396 4.266,20.643 42.393,22.326 23.492,23.056 24.725,23.221 28.09,23.274 0.647,23.605 4.266,23.643 17.4,23.63 18.299,23.63 34.475,23.638 18.5,24.758 14.776,25.344 42.393,26.089 14.272,27.45 32.587,28.002 19.784,28.151 21.904,28.151 24.228,28.169 19.749,29.37 21.868,29.37 24.193,29.387 10.267,29.501 14.316,29.523 42.393,29.916 0.604,29.959 19.749,30.684 21.868,30.684 24.193,30.702 16.177,30.842 11.016,31.143 4.712,31.244 11.007,32.049 13.368,32.058 23.696,32.484 21.576,32.511 22.691,32.5 19.469,32.537 34.426,32.632 4.266,32.643 11.766,32.643 38.766,32.643 28.492,33.037 14.559,33.15 0.647,33.772 38.688,33.772 42.393,33.788 17.114,33.915 13.952,34.094 18.476,34.113 12.516,34.143 33.516,34.143 36.377,35.453 18.726,35.582 1.266,35.643 2.766,35.643 4.266,35.643 5.766,35.643 7.266,35.643 8.766,35.643 10.266,35.643 13.266,35.643 32.766,35.643 34.266,35.643 38.766,35.643 40.266,35.643 41.766,35.643 37.607,35.984 14.566,36 15.736,36.005 11.71,36.089 33.834,36.586 16.198,37.067 32.772,37.086 0.516,37.143 2.016,37.143 3.516,37.143 5.016,37.143 6.516,37.143 8.016,37.143 9.516,37.143 11.016,37.143 12.516,37.143 14.016,37.143 15.208,37.143 36.56,37.143 39.516,37.143 41.016,37.143 18.669,37.236 38.016,37.232 20.32,37.432 37.266,38.581 1.266,38.643 2.766,38.643 4.266,38.643 5.766,38.643 7.266,38.643 8.766,38.643 10.266,38.643 11.766,38.643 13.266,38.643 14.766,38.643 16.266,38.643 19.266,38.643 20.766,38.643 22.266,38.643 38.766,38.643 40.266,38.643 41.766,38.643 35.766,38.971 32.736,39.062 34.321,39.062 20.605,39.776 22.105,39.776 23.605,39.776 30.353,39.767 0.516,40.143 2.016,40.143 3.516,40.143 5.016,40.143 6.516,40.143 8.016,40.143 9.516,40.143 16.182,40.143 18.622,40.152 32.016,40.143 33.516,40.143 35.016,40.143 36.516,40.143 38.016,40.143 39.516,40.143 41.016,40.143 1.266,41.643 2.766,41.643 4.266,41.643 5.766,41.643 7.266,41.643 8.766,41.643 10.266,41.643 11.766,41.643 16.266,41.643 19.266,41.643 25.266,41.643 26.766,41.643 28.266,41.643 29.766,41.643 31.266,41.643 32.766,41.643 34.266,41.643 35.766,41.643 37.266,41.643 38.766,41.643 40.266,41.643 41.766,41.643 0.516,43.143 2.016,43.143 3.516,43.143 5.016,43.143 6.516,43.143 8.016,43.143 9.516,43.143 11.016,43.143 17.016,43.143 18.588,43.143 24.516,43.143 26.016,43.143 27.516,43.143 29.016,43.143 30.516,43.143 32.016,43.143 33.516,43.143 35.016,43.143 36.516,43.143 38.016,43.143 39.516,43.143 41.016,43.143 1.266,44.643 2.766,44.643 4.266,44.643 5.766,44.643 7.266,44.643 8.766,44.643 10.266,44.643 11.766,44.643 16.266,44.643 19.266,44.643 25.266,44.643 26.766,44.643 28.266,44.643 29.766,44.643 31.266,44.643 32.766,44.643 34.266,44.643 35.766,44.643 37.266,44.643 38.766,44.643 40.266,44.643 41.766,44.643
GPIO2: CN1.8 U1.8 | length 27.6
  Top Layer w0.2: v1(11.762,29.629) 11.762,29.182 14.249,26.695 14.44,26.695 16.518,24.617 16.518,23.735 18.595,21.657 23,21.657 24.072,22.729 24.072,24.4 22.719,25.753 22.719,26.228 22.69,26.257 22.69,27.187 U1.8@22.645,27.233
  Internal 2 w0.2: v1(8.171,29.978) 8.257,29.978 8.488,30.209 10.548,30.209 11.128,29.629 v1(11.762,29.629)
  Bottom Layer w0.2: CN1.8@6.398,29.978 v1(8.171,29.978)
GPIO3/BOOT0: CN1.9 R1.1 U1.34 | length 26.9
  Top Layer w0.2: v1(10.258,28.751) 10.277,28.77 R1.1@11.125,28.77 ; U1.34@20.145,33.983 20.145,34.854 20.295,35.004 20.295,35.753 20.33,35.789 v1@20.33,35.837
  Bottom Layer w0.2: CN1.9@2.334,28.708 3.991,28.708 4.636,29.353 8.547,29.353 9.157,28.743 10.452,28.743 10.826,29.117 11.495,29.117 11.534,29.079 11.99,29.079 12.028,29.117 12.855,29.117 13.867,30.129 16.277,30.129 16.798,30.651 16.798,31.006 17.747,31.956 17.747,35.556 18.463,36.271 19.943,36.271 v1(20.308,35.906)
GPIO5/JTMS/SWDIO: CN1.13 R2.2 U1.27 | length 69.9
  Top Layer w0.2: U1.27@23.645,33.983 23.645,34.417 24.524,35.297 24.838,35.297 25.235,35.694 v1(25.235,36.643)
  Internal 1 w0.21: v1(14.748,23.63) 14.748,21.457 14.631,21.339 14.631,14.862 15.888,13.605 v1(15.888,11.497) ; v1(28.393,22.382) 28.393,22.488 28.948,23.043 28.948,23.084 29.803,23.938 29.803,26.059 29.755,26.107 29.755,26.567 29.803,26.614 29.803,26.62 30.125,26.942 30.125,27.643 30.875,28.393 30.875,31.527 30.88,31.532 30.88,33.185 30.766,33.3 30.766,35.278 v1(30.061,35.982)
  Bottom Layer w0.2: CN1.13@2.334,26.168 4.067,26.168 4.712,26.813 9.894,26.813 ; v1(25.235,36.643) 25.469,36.877 29.167,36.877 v1(30.061,35.982)
  Bottom Layer w0.21: 9.894,26.813 10.078,26.813 10.282,26.609 11.726,26.609 14.705,23.63 v1(14.748,23.63) ; v1@14.748,23.587 14.748,23.43 15.248,22.93 20.759,22.93 21.564,22.125 23.836,22.125 24.352,22.641 28.075,22.641 28.334,22.382 v1(28.393,22.382) ; v1(15.888,11.497) 19.208,11.497 19.529,11.176 v1@19.605,11.176 ; R2.2@19.605,10.328 v1@19.605,11.176 ; v1(19.634,11.176) v1@19.605,11.176
GPIO6/JTCK/SWCLK: CN1.15 R3.2 U1.26 | length 70.2
  Top Layer w0.2: U1.26@24.145,33.983 24.145,34.405 24.655,34.916 25.032,34.916 25.926,35.81 v1(25.926,36.236)
  Internal 1 w0.21: v1(13.908,21.98) 13.908,20.011 14.132,19.787 14.132,14.802 15.075,13.859 15.075,10.811 v1(15.101,10.786) ; v1(27.953,35.627) 28.969,35.627 30.046,34.55 30.046,33.001 30.16,32.887 30.16,31.83 30.155,31.825 30.155,28.691 29.405,27.942 29.405,27.241 28.639,26.475 v1(28.639,23.945)
  Internal 2 w0.21: v1(15.101,10.786) 16.128,10.786 16.36,11.018 19.007,11.018 19.404,10.621 20.248,10.621 v1(20.803,11.176)
  Bottom Layer w0.2: CN1.15@2.334,24.898 3.991,24.898 4.636,25.543 9.716,25.543 ; v1(25.926,36.236) 26.135,36.236 26.745,35.627 v1(27.953,35.627)
  Bottom Layer w0.21: 9.716,25.543 11.996,25.543 13.908,23.631 13.908,21.914 13.974,21.914 14.463,21.425 23.807,21.425 24.659,22.278 26.672,22.278 27.123,21.827 28.63,21.827 28.948,22.146 28.948,23.627 28.639,23.937 v1(28.639,23.945) ; R3.2@20.887,10.328 v1@20.887,11.176
GPIO11: CN1.24 U1.4 | length 23.5
  Top Layer w0.21: U1.4@20.645,27.233 20.645,26.51 20.564,26.43 20.564,25.075 20.676,24.962 v1(20.676,23.63)
  Internal 1 w0.21: v1(20.676,23.63) 20.706,23.63 21.809,22.527 21.809,21.298 21.614,21.103 v1(21.614,19.768)
  Bottom Layer w0.2: CN1.24@6.398,19.818 6.536,19.956 21.318,19.956 21.506,19.768 v1(21.614,19.768)
GPIO12: CN1.26 U1.5 | length 22.3
  Top Layer w0.21: v1(21.119,25.543) 21.19,25.614 21.19,27.188 U1.5@21.145,27.233
  Internal 1 w0.21: v1(19.025,19.406) 19.025,23.791 19.985,24.752 20.328,24.752 v1(21.119,25.543)
  Bottom Layer w0.2: CN1.26@6.398,18.548 6.456,18.491 8.116,18.491 8.635,19.01 8.785,19.01 8.806,19.032 10.227,19.032 10.593,18.666 18.322,18.666 19.025,19.369 v1(19.025,19.406)
GPIO14: CN1.29 SB30.1 | length 13.2
  Bottom Layer w0.2: CN1.29@2.334,16.008 3.953,16.008 4.572,15.39 7.899,15.39 7.961,15.452 11.662,15.452 13.837,17.628 SB30.1@14.304,17.628
GPIO15/OSC32_IN: CN1.33 SB37.2 | length 44.2
  Internal 1 w0.21: v1(26.137,15.646) 26.051,15.646 25.725,15.973 25.725,18.715 27.072,20.062 27.072,24.012 27.919,24.859 27.919,26.773 28.685,27.539 28.685,28.49 29.159,28.964 v1(29.159,29.87)
  Bottom Layer w0.2: CN1.33@2.334,13.468 3.737,13.468 4.382,14.113 8.073,14.113 8.268,13.918 8.268,13.488 8.551,13.205 11.221,13.205 12.594,14.578 12.594,15.863 13.546,16.815 22.78,16.815 22.922,16.672 23.966,16.672 24.109,16.815 24.819,16.815 25.567,16.067 25.709,16.067 26.129,15.646 v1(26.137,15.646)
  Bottom Layer w0.21: SB37.2@29.062,30.612 29.057,30.607 29.057,30.078 29.159,29.976 v1(29.159,29.87)
GPIO16/OSC32_OUT: CN1.35 SB38.2 | length 39.1
  Internal 1 w0.21: v1(21.222,15.476) 21.222,16.628 21.775,17.18 21.775,17.39 21.689,17.476 21.689,17.826 v1(21.614,17.9) ; v1(25.986,19.761) 25.986,19.789 26.649,20.452 26.649,24.284 27.559,25.194 27.559,27.185 28.13,27.756 v1(28.13,27.769)
  Bottom Layer w0.2: CN1.35@2.334,12.198 3.966,12.198 4.61,12.843 11.715,12.843 13.557,14.685 20.432,14.685 v1(21.222,15.476)
  Bottom Layer w0.21: v1(21.614,17.9) 22.691,17.9 23.214,17.377 23.674,17.377 24.197,17.9 24.822,17.9 25.64,18.719 25.64,19.338 25.986,19.683 v1(25.986,19.761) ; v1(28.13,27.769) 28.205,27.843 28.409,27.843 28.606,28.04 28.606,28.251 28.911,28.557 SB38.2@28.911,28.569
GPIO17: CN1.36 SB9.1 | length 9.4
  Internal 1 w0.21: v1(8.256,12.198) 9.363,11.091 9.363,8.453 9.36,8.45 v1(9.36,6.214)
  Bottom Layer w0.2: CN1.36@6.398,12.198 v1(8.256,12.198)
  Bottom Layer w0.21: v1(9.36,6.214) 9.515,6.214 9.579,6.277 SB9.1@10.384,6.277
GPIO18: CN1.38 U1.12 | length 32.5
  Top Layer w0.2: U1.12@24.645,27.233 24.645,27.108 25.145,26.607 v1(25.211,26.607)
  Internal 1 w0.21: v1(23.335,14.926) 23.335,16.398 24.588,17.651 24.588,20.14 24.53,20.198 24.53,22.241 25.28,22.991 25.28,26.538 v1(25.211,26.607)
  Bottom Layer w0.2: CN1.38@6.398,10.928 6.667,11.197 7.806,11.197 7.813,11.204 11.379,11.204 12.101,11.925 12.101,12.657 13.686,14.242 22.652,14.242 v1(23.335,14.926)
GPIO21: CN1.42 SB17.1 SB19.1 | length 4.9
  Bottom Layer w0.2: CN1.42@6.398,8.388 SB17.1@10.375,8.388 ; SB17.1@10.428,8.381 SB19.1@10.428,9.309
GPIO22: CN1.44 SB14.1 | length 4
  Bottom Layer w0.2: CN1.44@6.398,7.118 10.283,7.118 10.369,7.205 SB14.1@10.384,7.205
GPIO23: CN1.45 R9.1 SB21.1 | length 27.6
  Bottom Layer w0.2: CN1.45@2.334,5.848 4.274,5.848 4.925,5.198 8.522,5.198 9.337,4.382 15.987,4.382 16.506,4.901 SB21.1@16.506,5.512 ; SB21.1@16.506,5.603 SB21.1@16.506,5.512 ; R9.1@27.024,4.35 27.024,5.009 25.952,6.081 18.164,6.081 17.596,5.512 SB21.1@16.506,5.512
GPIO24: CN1.47 R8.2 U1.1 | length 53.4
  Top Layer w0.21: U1.1@19.145,27.233 19.145,23.58 20.192,22.533 20.192,22.483 20.339,22.336 v1(20.339,22.23)
  Internal 1 w0.21: v1(17.336,4.537) 18.123,5.325 v1(18.123,8.855) 18.177,8.909 18.822,8.909 19.7,9.788 20.636,9.788 21.453,10.605 21.453,12.916 20.351,14.017 20.351,22.218 v1(20.339,22.23)
  Bottom Layer w0.2: CN1.47@2.334,4.578 4.102,4.578 4.728,3.953 16.777,3.953 17.336,4.512 v1(17.336,4.537)
  Bottom Layer w0.21: v1(18.123,8.855) 19.165,7.814 26.353,7.814 26.527,7.988 26.527,9.818 26.017,10.328 R8.2@25.922,10.328
GPIO26: CN2.5 U1.14 | length 18.1
  Top Layer w0.21: U1.14@25.27,28.358 25.315,28.313 25.6,28.313 25.898,28.015 25.898,27.246 26.291,26.854 26.981,26.854 v1(27,26.873)
  Bottom Layer w0.21: v1(27,26.873) 27.006,26.873 27.667,26.212 29.627,26.212 30.066,25.772 30.531,25.772 30.865,26.107 30.865,28.002 30.518,28.349 30.518,30.245 31.066,30.792 32.452,30.792 32.908,31.248 CN2.5@36.624,31.248
GPIO28: CN2.7 U1.30 | length 25
  Top Layer w0.2: U1.30@22.145,33.983 22.145,34.543 23.025,35.424 23.025,36.211 v1(23,36.211)
  Internal 1 w0.21: v1(34.453,37.718) 34.528,37.643 34.528,36.305 35.061,35.771 35.061,30.434 34.887,30.259 v1@34.887,30.153
  Bottom Layer w0.2: v1(23,36.211) 23,36.668 24.494,38.162 33.908,38.162 34.352,37.718 v1(34.453,37.718)
  Bottom Layer w0.21: v1(34.885,30.153) 36.45,30.153 CN2.7@36.624,29.978
GPIO29: CN2.9 U1.31 | length 29.8
  Top Layer w0.2: U1.31@21.645,33.983 21.645,34.602 22.289,35.246 22.289,36.795 v1(22.263,36.821)
  Internal 1 w0.21: v1(35.689,38.007) 35.763,37.932 35.763,37.717 35.791,37.689 35.791,37.015 37,35.806 37,31.014 v1(38.764,29.251)
  Bottom Layer w0.2: v1(22.263,36.821) 23.955,38.512 35.183,38.512 v1(35.689,38.007)
  Bottom Layer w0.21: CN2.9@36.624,28.708 38.222,28.708 v1(38.764,29.251)
GPIO30: CN2.10 SB13.2 | length 9.3
  Bottom Layer w0.2: 32.276,29.662 33.551,29.662 35.131,28.083 38.338,28.083 38.963,28.708 CN2.10@40.688,28.708
GPIO31: CN2.11 SB10.2 | length 5.2
  Bottom Layer w0.21: SB10.2@32.077,28.905 33.433,28.905 34.899,27.438 CN2.11@36.624,27.438
GPIO32: CN2.12 R4.2 SB11.2 | length 35.8
  Internal 1 w0.21: v1(30.239,11.802) 29.562,12.479 29.562,15.337 30.624,16.399 31.901,16.399 32.817,17.315 32.817,19.74 33.191,20.113 33.191,25.574 33.788,26.171 v1(33.788,26.201)
  Internal 2 w0.21: v1(22.149,11.176) 22.254,11.176 22.537,11.458 23.587,11.458 24.424,10.621 25.194,10.621 26.24,11.667 v1(26.24,11.75)
  Bottom Layer w0.2: R4.2@22.092,10.302 22.149,10.359 v1(22.149,11.176) ; v1(26.24,11.75) 26.292,11.802 v1(30.239,11.802) ; SB11.2@32.853,26.641 32.943,26.641 32.981,26.679 33.114,26.546 33.335,26.546 33.68,26.201 v1(33.788,26.201) ; v1@33.694,26.186 33.911,26.186 34.538,26.813 v1(38.646,26.813) 38.672,26.788 39.323,27.438 CN2.12@40.688,27.438
GPIO33: CN2.13 SB7.2 | length 4
  Bottom Layer w0.2: SB7.2@32.938,25.794 33.405,25.794 33.563,25.636 34.001,25.636 34.533,26.168 CN2.13@36.624,26.168
GPIO34: CN2.15 SB33.1 | length 3.9
  Bottom Layer w0.2: SB33.1@32.844,24.814 32.844,24.804 32.954,24.694 36.42,24.694 CN2.15@36.624,24.898
GPIO35: CN2.16 U1.17 | length 17.5
  Top Layer w0.2: U1.17@25.27,29.858 25.276,29.852 25.891,29.852 v1@25.898,29.858
  Internal 2 w0.2: v1(25.908,29.845) 25.911,29.845 27.04,28.716 34.851,28.716 38.27,25.298 v1(38.756,25.298)
  Bottom Layer w0.2: v1(38.756,25.298) 38.864,25.298 38.995,25.167 40.42,25.167 CN2.16@40.688,24.898
GPIO36: CN2.18 U1.16 | length 17.8
  Top Layer w0.2: U1.16@25.27,29.358 25.32,29.308 25.602,29.308 27.156,27.754 v1(27.156,27.738)
  Internal 2 w0.2: v1(27.156,27.738) 27.843,27.051 34.321,27.051 37.734,23.638 v1(38.963,23.638)
  Bottom Layer w0.2: v1(38.963,23.638) 40.679,23.638 CN2.18@40.688,23.628
GPIO37: CN2.21 SB26.1 | length 4.7
  Bottom Layer w0.2: SB26.1@32.824,22.679 34.119,22.679 34.977,21.821 34.977,21.44 35.167,21.25 36.005,21.25 36.167,21.088 CN2.21@36.624,21.088
GPIO38: CN2.22 R5.2 SB35.1 | length 34.4
  Internal 1 w0.21: v1(34.151,8.964) 34.151,8.982 34.633,9.465 34.633,13.505 33.897,14.242 33.897,16.47 34.633,17.207 34.633,18.964 34.343,19.255 v1(34.343,21.581)
  Internal 2 w0.21: v1(23.376,10.782) 23.389,10.782 24.01,10.161 26.468,10.161 v1(27.464,9.165)
  Bottom Layer w0.2: R5.2@23.376,10.328 v1(23.376,10.782) ; SB35.1@32.829,21.708 34.025,21.708 34.076,21.657 34.266,21.657 v1(34.343,21.581) 34.395,21.528 34.395,21.185 35.126,20.454 38.351,20.454 38.985,21.088 CN2.22@40.688,21.088
  Bottom Layer w0.21: v1(27.464,9.165) 27.569,9.165 27.727,9.008 34.107,9.008 v1(34.151,8.964)
GPIO39: CN2.23 SB28.1 | length 8.7
  Internal 1 w0.21: v1(31.662,18.825) 31.662,19.949 v1(32.636,20.923)
  Bottom Layer w0.2: v1(32.636,20.923) 32.645,20.913 33.497,20.913 34.592,19.818 CN2.23@36.624,19.818
  Bottom Layer w0.21: SB28.1@30.282,18 31.047,18.765 31.602,18.765 v1(31.662,18.825)
GPIO40: CN2.24 U1.9 | length 22.4
  Top Layer w0.2: U1.9@23.145,27.233 23.19,27.188 23.19,25.818 23.435,25.573 23.435,25.555 23.757,25.233 23.775,25.233 25.666,23.342 v1(25.666,21.723)
  Internal 2 w0.2: v1(25.666,21.723) 27.016,20.373 38.115,20.373 v1(38.688,19.8)
  Bottom Layer w0.2: v1(38.688,19.8) 40.67,19.8 CN2.24@40.688,19.818
GPIO41: CN2.25 SB22.1 SB31.2 | length 13.7
  Internal 1 w0.21: v1(33.795,13.427) 33.49,13.732 33.49,16.678 33.871,17.059 v1(33.871,18.533)
  Bottom Layer w0.2: SB31.2@32.885,19.71 32.895,19.7 33.31,19.7 33.635,19.375 33.635,18.85 33.871,18.614 v1(33.871,18.533) ; v1@33.871,18.548 CN2.25@36.624,18.548
  Bottom Layer w0.21: SB22.1@30.266,13.988 30.827,13.427 v1(33.795,13.427)
GPIO42: CN2.27 SB36.2 | length 4
  Bottom Layer w0.2: SB36.2@32.921,17.941 33.171,17.941 33.834,17.278 CN2.27@36.624,17.278
GPIO43: CN2.28 SB27.1 | length 11.5
  Bottom Layer w0.2: SB27.1@30.31,17.075 30.31,16.582 30.696,16.196 33.668,16.196 34.125,16.653 38.494,16.653 39.119,17.278 CN2.28@40.688,17.278
GPIO44: CN2.29 SB20.2 | length 42.2
  Top Layer w0.2: v1(26.28,17.501) 26.357,17.425 26.357,17.106 v1(27.445,16.018)
  Internal 1 w0.21: v1(27.394,35.043) 28.969,35.043 29.686,34.326 29.686,32.852 29.8,32.738 29.8,31.98 29.795,31.974 29.795,28.84 29.045,28.091 29.045,27.39 28.279,26.624 28.279,24.485 27.471,23.677 27.471,19.197 27.445,19.171 v1(27.445,16.018)
  Bottom Layer w0.2: v1(21.735,36.225) 21.735,36.194 22.302,35.627 26.2,35.627 26.784,35.043 v1(27.394,35.043) ; v1(26.28,17.501) 26.28,17.578 25.881,17.977 25.881,18.458 26.673,19.25 26.837,19.25 27.119,19.531 SB20.2@27.133,19.531
  Bottom Layer w0.21: v1(27.445,16.018) 28.639,16.018 28.867,15.789 34.227,15.789 34.446,16.008 CN2.29@36.624,16.008
GPIO45: CN2.30 SB24.1 | length 8.1
  Bottom Layer w0.2: 32.851,15.354 32.88,15.383 33.708,15.383 33.713,15.388 34.252,15.388 34.257,15.383 38.469,15.383 39.094,16.008 CN2.30@40.688,16.008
